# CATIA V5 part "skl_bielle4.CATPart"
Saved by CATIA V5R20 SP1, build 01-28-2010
Part number: skl_bielle4
Publications: "Plan_ref", "PointE", "Plan_pivot_E", "axe_ref", "axe_pivot_E", "PointB", "axe_pivot_B", "axe_pivot_D", "PointD", "Plan_pivot_B"
Bounding box of the stored display mesh (mm): x -40 to 40, y 0 to 250, z -220 to 30
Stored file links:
  C:\Users\Fabien-port\Desktop\test\skl_bielle4.CATPart
  C:\Users\Fabien-port\Desktop\test\ass_skl_mecanisme_a_coulisseau.CATProduct
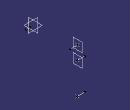
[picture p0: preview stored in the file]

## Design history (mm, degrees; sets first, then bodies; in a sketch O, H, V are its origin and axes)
Set1
  Plane1 "Plan_ref": linked copy from another document
  Point1 "PointE": linked copy from another document
  Line1 "axe_ref": linked copy from another document
  Point2 "PointB": linked copy from another document
  Point3 "PointD": linked copy from another document
Set2
  Plane2 "Plan_pivot_E": type OffsetPt, RefPlane Plane1, RefPoint Point1
  Line2 "axe_pivot_E": type PtDir, RefPoint Point1, Direction Line1, Start 0, End 40
  Line3 "axe_pivot_B": type PtDir, RefPoint Point2, Direction Line1, Start 0, End 40
  Line4 "axe_pivot_D": type PtDir, RefPoint Point3, Direction Line1, Start 0, End 40
  Plane3 "Plan_pivot_B": type OffsetPt, RefPlane Plane1, RefPoint Point2
Body1 (main body)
